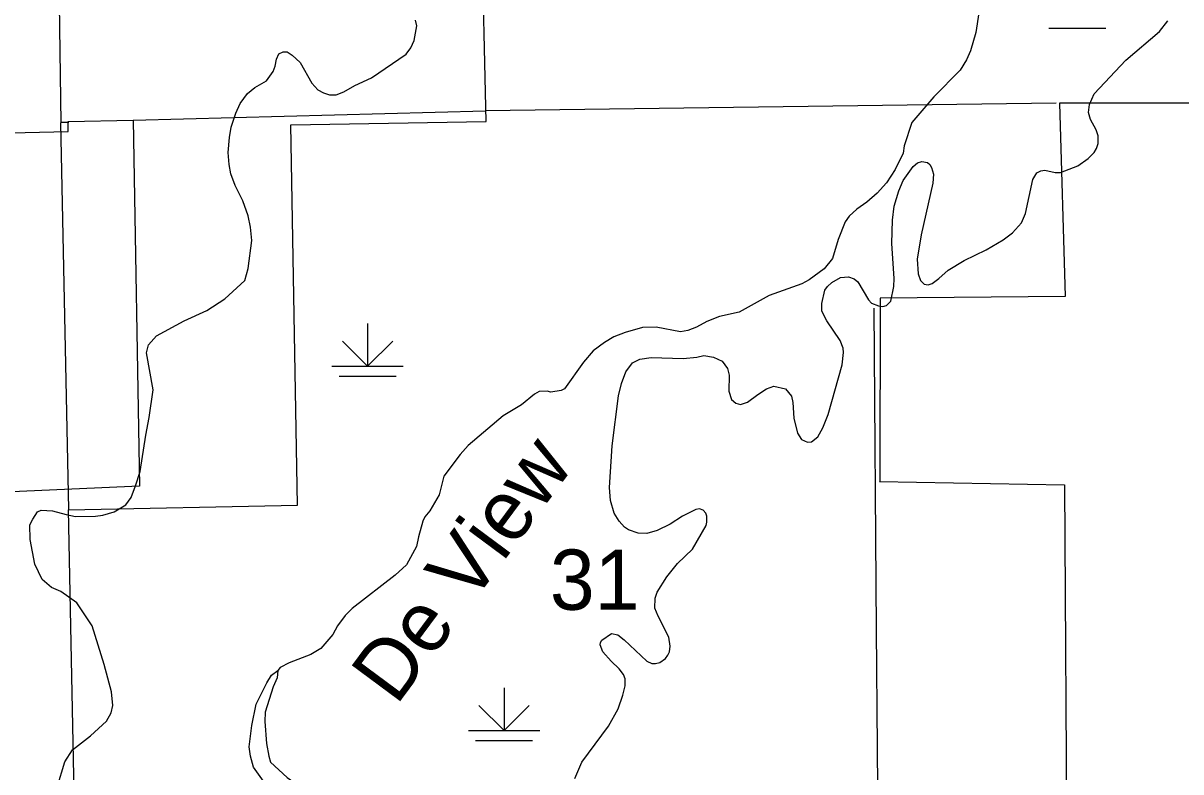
# Model space of a CAD drawing. Extents: x 1084508 to 1142749, y 1057638 to 1093403.
# Drawn here: x 1095928 to 1098477, y 1077367 to 1079015 of the extents above; entities that cross this region are included whole.
import ezdxf

# ---------------------------------------------------------------- set-up
doc = ezdxf.new("R2010")
doc.units = 0
for name, color, linetype in [('Level 35', 7, 'Continuous'), ('Level 4', 7, 'Continuous'), ('Level 44', 7, 'Continuous'), ('Level 47', 7, 'Continuous'), ('Level 5', 7, 'Continuous'), ('Level 7', 7, 'Continuous')]:
    doc.layers.add(name, color=color, linetype=linetype)

msp = doc.modelspace()

# ---------------------------------------------------------------- linework, layer by layer
at = {"layer": 'Level 35'}
for points in [[(1098031.7, 1079038.1), (1098024.9, 1078994.6), (1098013.5, 1078954.5), (1098004.3, 1078934.2), (1097990.5, 1078911.9), (1097932.5, 1078853.2), (1097884.4, 1078796.6), (1097867.5, 1078745.4), (1097865.1, 1078729.2), (1097847.6, 1078692.9), (1097828.1, 1078663.9), (1097807.8, 1078640.7), (1097785, 1078621.4), (1097762.8, 1078605.3), (1097746.2, 1078590.4), (1097737.3, 1078577.7), (1097721.8, 1078538.6), (1097709.8, 1078497.4), (1097691, 1078474.5), (1097658.4, 1078450.4), (1097641.9, 1078441.1), (1097570, 1078415.6), (1097504.3, 1078379.2), (1097460.7, 1078369.7), (1097432.9, 1078358.4), (1097410.2, 1078345.7), (1097391.3, 1078338.6), (1097374.8, 1078336), (1097321.1, 1078345.9), (1097291.3, 1078345.1), (1097252.7, 1078334.3), (1097228, 1078324.4), (1097207.8, 1078312.1), (1097182.5, 1078293.7), (1097161.6, 1078268.5), (1097119.3, 1078210.2), (1097111.9, 1078206.7), (1097089.4, 1078202.9), (1097081.1, 1078205), (1097063.8, 1078204.6), (1097053.4, 1078198.5), (1097024.9, 1078174.8), (1096984.2, 1078150.6), (1096907.2, 1078085.5)], [(1096907.2, 1078085.5), (1096889.7, 1078065.4), (1096854, 1078017.6), (1096843.8, 1077976.5), (1096822.6, 1077941.9), (1096811.8, 1077928.2), (1096807.2, 1077918.9), (1096798, 1077884.4), (1096793.8, 1077863.1), (1096771.9, 1077822.5), (1096746.5, 1077800), (1096652.1, 1077726.4), (1096636.7, 1077711.2), (1096619.7, 1077688.5), (1096609.2, 1077669.1), (1096583.1, 1077638.7), (1096560.7, 1077625.5), (1096513.4, 1077606.8), (1096493.7, 1077596.8), (1096488.3, 1077590.3)], [(1096457, 1077346.2), (1096435, 1077377.2), (1096427.9, 1077401.8), (1096424.9, 1077421.8), (1096430.8, 1077469), (1096440.8, 1077515.8), (1096464.3, 1077563.1), (1096474.6, 1077579.9), (1096488.3, 1077590.3)], [(1096488.3, 1077590.3), (1096487.1, 1077573.8), (1096478.2, 1077554.2), (1096460.4, 1077498.3), (1096459.6, 1077478.1), (1096463.3, 1077429.1), (1096468.2, 1077401.2), (1096472.5, 1077388.2), (1096508.9, 1077354.4), (1096532.9, 1077337.8), (1096554.8, 1077331.4), (1096565.3, 1077321.2), (1096567.9, 1077311.8), (1096565.6, 1077290.9), (1096566.2, 1077263.8), (1096564.4, 1077253.3), (1096553.7, 1077223.9), (1096543.7, 1077184.1), (1096547, 1077045.5), (1096552.9, 1077009.8), (1096554.6, 1076978.4), (1096552, 1076933.8), (1096540, 1076868.1), (1096528.1, 1076844.6)]]:
    msp.add_lwpolyline(points, dxfattribs=at)
at = {"layer": 'Level 4'}
for points in [[(1095991.4, 1080158.3), (1096010.8, 1078795.5)], [(1096028, 1077944.7), (1096010.8, 1078795.5)]]:
    msp.add_lwpolyline(points, dxfattribs=at)
at = {"layer": 'Level 44'}
for p, q in [((1098186, 1079004.4), (1098311.6, 1079004.4)), ((1096685.8, 1078353.9), (1096685.8, 1078259.8)), ((1096685.8, 1078259.8), (1096630.3, 1078315.3)), ((1096685.8, 1078259.8), (1096741.2, 1078315.3)), ((1096607.3, 1078259.8), (1096764.2, 1078259.8)), ((1096623, 1078238.4), (1096748.5, 1078238.4)), ((1096986.3, 1077551.9), (1096986.3, 1077457.8)), ((1096986.3, 1077457.8), (1096930.8, 1077513.3)), ((1096986.3, 1077457.8), (1097041.8, 1077513.3)), ((1096907.8, 1077457.8), (1097064.8, 1077457.8)), ((1096923.5, 1077436.4), (1097049.1, 1077436.4))]:
    msp.add_line(p, q, dxfattribs=at)
at = {"layer": 'Level 47'}
for points in [[(1096021.9, 1077933.2), (1096042.5, 1077929.1), (1096086.5, 1077929.6), (1096103.1, 1077932.2), (1096127.9, 1077939.6), (1096153.7, 1077955.1), (1096165, 1077971.1), (1096174.9, 1077996.4), (1096184.9, 1078028), (1096197.3, 1078108.3), (1096205.1, 1078147.1), (1096213.9, 1078207.6), (1096199.1, 1078289.6), (1096203.4, 1078307.1), (1096221.4, 1078327.1), (1096281.7, 1078359.9), (1096331.7, 1078382.5), (1096371.5, 1078408.4), (1096415.4, 1078448.4), (1096423.1, 1078474.9), (1096430.9, 1078536.7), (1096428.1, 1078566.2), (1096422.9, 1078591.2), (1096411.2, 1078624.1), (1096394.7, 1078657.8), (1096385.1, 1078683.2), (1096380.8, 1078703.9), (1096378.7, 1078730.2), (1096381.7, 1078763.2), (1096385.5, 1078786), (1096395.8, 1078816.7), (1096405.3, 1078838.2), (1096421.7, 1078860), (1096437.5, 1078873.6), (1096463.3, 1078888.2), (1096478.2, 1078908.4), (1096482.4, 1078920.3), (1096485.5, 1078936.1), (1096490.7, 1078947.7), (1096500.2, 1078951.9), (1096508.7, 1078951.9), (1096520, 1078944.8), (1096537.4, 1078928.2), (1096563.5, 1078883), (1096576.4, 1078868.7), (1096588.9, 1078861.7), (1096602.3, 1078857.2), (1096616.8, 1078857.5), (1096633.5, 1078864.2), (1096657.8, 1078878.1), (1096694.5, 1078895.1), (1096771.2, 1078946.5), (1096781.4, 1078960.5), (1096788.5, 1078976.9), (1096794.1, 1079009.3), (1096791.7, 1079021.5)], [(1097918.9, 1078708.6), (1097923.8, 1078703.8), (1097927.3, 1078697.7), (1097931.7, 1078682.4), (1097930.7, 1078662.9), (1097905.1, 1078549), (1097895.8, 1078495.9), (1097898.2, 1078463.6), (1097903.6, 1078448.4), (1097911.2, 1078440.6), (1097920.1, 1078438.8), (1097928.8, 1078441.7), (1097943.4, 1078452.7), (1097964.3, 1078471.6), (1097999.5, 1078492.7), (1098048.1, 1078516.3), (1098085.2, 1078538.1), (1098105.9, 1078553.2), (1098125.4, 1078575.5), (1098134.5, 1078596.4), (1098150.9, 1078670.8), (1098159.4, 1078686), (1098168, 1078690.2), (1098177, 1078691.8), (1098200, 1078686.2), (1098211.6, 1078686.1), (1098249.9, 1078701.1), (1098272.2, 1078717.2), (1098285.4, 1078730.7), (1098290.7, 1078739.1), (1098294.3, 1078750.3), (1098294.8, 1078767), (1098290.4, 1078780), (1098277.4, 1078803.4), (1098273.3, 1078818.3), (1098275.3, 1078835.7), (1098285.6, 1078859.2), (1098355.2, 1078933.5), (1098429.8, 1078996.4), (1098448.2, 1079019.9)], [(1097352.1, 1077911.9), (1097323.8, 1077898.1), (1097301.1, 1077891.4), (1097281.9, 1077892.7), (1097260.5, 1077900), (1097251.4, 1077905.5), (1097239.8, 1077919.2), (1097228.6, 1077936.3), (1097220.4, 1077964.3), (1097218.5, 1077993.2), (1097224.7, 1078084.8), (1097238.3, 1078195.1), (1097244.9, 1078221.8), (1097254.5, 1078247.8), (1097269, 1078267.6), (1097285.6, 1078275.6), (1097310.6, 1078278.9), (1097380.6, 1078277), (1097410.6, 1078279.9), (1097426.5, 1078283.5), (1097447.5, 1078280), (1097466.8, 1078270.8), (1097478.5, 1078254.9), (1097482, 1078240.3), (1097481.4, 1078204.7), (1097487.2, 1078186.6), (1097496.8, 1078178.3), (1097506.9, 1078175.6), (1097522.1, 1078180.6), (1097545, 1078197.7), (1097564.5, 1078209.9), (1097580, 1078215.7), (1097605.7, 1078210.5), (1097619.1, 1078194.1), (1097621.9, 1078180.4), (1097624.1, 1078145.5), (1097632.2, 1078112.8), (1097641, 1078098.7), (1097654.5, 1078093), (1097663.3, 1078093.7), (1097677.6, 1078104.4), (1097688, 1078124.1), (1097700.2, 1078153.9), (1097730.5, 1078263.3), (1097734, 1078290), (1097732.9, 1078299.7), (1097726.5, 1078316.4), (1097696.8, 1078359.5), (1097686.4, 1078381.4), (1097685.7, 1078398), (1097692.5, 1078427), (1097698.4, 1078435.5), (1097707.8, 1078444.4), (1097727.1, 1078455), (1097745, 1078456.8), (1097757.1, 1078452.6), (1097765.3, 1078445.7), (1097788.5, 1078406.4), (1097795.1, 1078398.8), (1097810.8, 1078392.9), (1097820.3, 1078391.5), (1097828.4, 1078393.7), (1097837.7, 1078403.3), (1097844.4, 1078435.7), (1097845.2, 1078453.4), (1097840.5, 1078530), (1097841.6, 1078581.7), (1097845.2, 1078612.1), (1097855.7, 1078646), (1097865.3, 1078668.8), (1097887.2, 1078699.7), (1097896.9, 1078707.7), (1097905.9, 1078710.9), (1097918.9, 1078708.6)], [(1096002.1, 1077333.5), (1096019, 1077389), (1096036.1, 1077415.3), (1096076, 1077446.6), (1096110.8, 1077478.9), (1096121.1, 1077496.7), (1096124.8, 1077513.3), (1096122.3, 1077543.1), (1096105.9, 1077603.3), (1096079.7, 1077688.5), (1096045.8, 1077739.4), (1096010.4, 1077764.4), (1095989.6, 1077773), (1095969.7, 1077790.5), (1095953.2, 1077824.1), (1095942.8, 1077878.2), (1095942.6, 1077911), (1095949, 1077923.2), (1095959.1, 1077939.4), (1095967.1, 1077943.2), (1095992.3, 1077941.8), (1096021.9, 1077933.2)], [(1097142.4, 1077352.6), (1097157.8, 1077388.6), (1097216.5, 1077467.7), (1097237.8, 1077505.5), (1097248, 1077535.9), (1097253.1, 1077556.3), (1097253.3, 1077571.7), (1097249.4, 1077581.3), (1097239.7, 1077594.1), (1097222, 1077610.4), (1097203.7, 1077631.3), (1097198, 1077646.4), (1097198.7, 1077651.5), (1097201.9, 1077657), (1097222.7, 1077671.8), (1097236.7, 1077668.6), (1097250.7, 1077657.9), (1097301, 1077610.7), (1097311.6, 1077605.8), (1097319.5, 1077605.3), (1097329.7, 1077607.6), (1097341.9, 1077616.3), (1097347.3, 1077623.8), (1097350.4, 1077631.5), (1097352.3, 1077643.9), (1097349.5, 1077663.6), (1097325.4, 1077710.1), (1097318.7, 1077727.1), (1097319.2, 1077749.2), (1097323.7, 1077762.3), (1097345.1, 1077796.3), (1097368, 1077826), (1097401.2, 1077857.1), (1097431.2, 1077909.5), (1097432.8, 1077916.5), (1097432.8, 1077930), (1097430.6, 1077936.5), (1097425, 1077943.2), (1097416.7, 1077945.7), (1097408.5, 1077944.7), (1097379.6, 1077930.2), (1097352.1, 1077911.9)]]:
    msp.add_lwpolyline(points, dxfattribs=at)
at = {"layer": 'Level 5'}
for points in [[(1096945.5, 1078822.6), (1098202, 1078839.8)], [(1096945.5, 1078821.2), (1096169.6, 1078800.5)], [(1096028.3, 1078796.8), (1096010.9, 1078796.3)], [(1097806.5, 1077680.1), (1097801.1, 1078387.6)], [(1097810.5, 1077158.2), (1097806.5, 1077680.1)]]:
    msp.add_lwpolyline(points, dxfattribs=at)
at = {"layer": 'Level 7'}
for points in [[(1094412.6, 1077603.3), (1094518.1, 1077606.7), (1094520.4, 1077492.8), (1094813, 1077501.2), (1094821.3, 1077065.5), (1095650.9, 1077105.1), (1095654.2, 1076707.7), (1096052.4, 1076698.5), (1096027.5, 1077943.8), (1096531.5, 1077954.1), (1096516.8, 1078791.1), (1096947.3, 1078798.9), (1096937.8, 1079217.9), (1097357.4, 1079227.2), (1097349.1, 1079641.1), (1097785.1, 1079648.9), (1097783.6, 1079865.8)], [(1098615.8, 1079759.8), (1098508.7, 1079608.2), (1098541.4, 1079494.8), (1098613.2, 1079507.6), (1098614, 1079265.1), (1098634.5, 1079265.5), (1098633.4, 1078839), (1098209.9, 1078838.8), (1098209.6, 1078839), (1098222, 1078413.7), (1097814.4, 1078409.9), (1097813.5, 1078006.7), (1097813.8, 1078006.7), (1097813.3, 1078006.5), (1098220.1, 1077998.5), (1098225.6, 1077158)], [(1094802.8, 1078739.9), (1095198.9, 1078753.5), (1095614.8, 1078767.2), (1096026.8, 1078776.6), (1096026.6, 1078798.5), (1096169.7, 1078801.4), (1096183.6, 1077996), (1095902.8, 1077983.8), (1095905.1, 1077106.6), (1095650.9, 1077105.1), (1095626.4, 1077515), (1095420.3, 1077511.9), (1095419.9, 1077930), (1094915.2, 1077913.8), (1094909.7, 1078006.1), (1094842.1, 1078004.8)]]:
    msp.add_lwpolyline(points, dxfattribs=at)

# ---------------------------------------------------------------- texts
at = {"layer": 'Level 35'}
msp.add_text('De View', height=132.58, rotation=53.4534, dxfattribs=at).set_placement((1096749.1, 1077510.8))
at = {"layer": 'Level 5'}
msp.add_text('31', height=132.58, dxfattribs=at).set_placement((1097087.3, 1077723.8))

doc.saveas('drawing.dxf')
